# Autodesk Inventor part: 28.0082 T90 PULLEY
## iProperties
Created: 2006-12
Document SubType Name: Modeling
Designer: Andy Moles
Part Number: 28.0082 T90 PULLEY
Material: Aluminum-6061
Mass: 364.841 g
Surface Area: 243.567 cm^2
Volume: 134.628 cm^3
Density: 2.71 g/cm^3
Author: Andy Moles
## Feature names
1. Extrusion1
2. Extrusion3
3. Extrusion4
4. Extrusion6
5. Mirror1
6. Extrusion7
